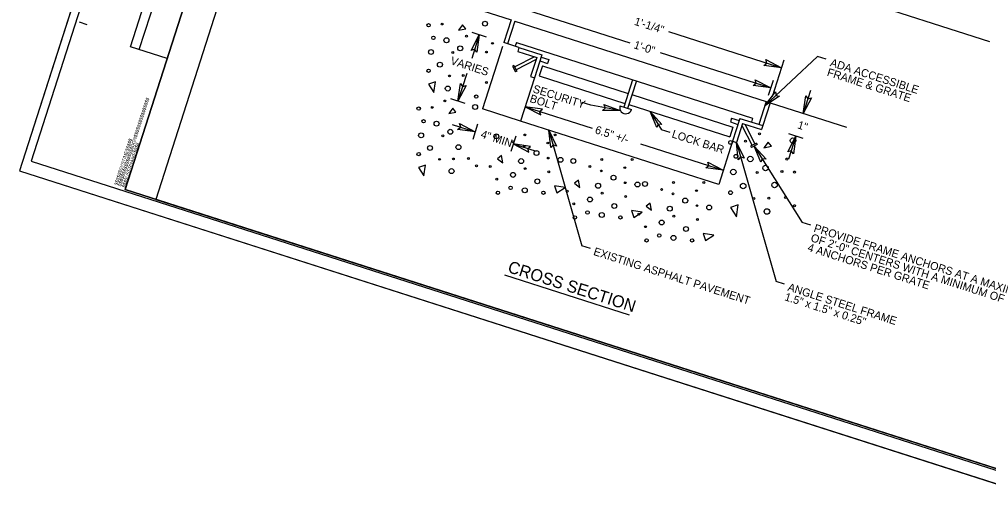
# Model space of a CAD drawing. Extents: x 928111 to 937215, y 684320 to 686530.
# Drawn here: x 933597.6 to 933658.2, y 684605.2 to 684635.2 of the extents above; entities that cross this region are included whole.
import ezdxf

# ---------------------------------------------------------------- set-up
doc = ezdxf.new("R2010")
doc.units = 0
for name, color, linetype in [('Default', 7, 'Continuous'), ('Exist Roads EOP', 7, 'Continuous'), ('Old_Level_2', 7, 'Continuous'), ('Prop Conc 5in Monolithic Keyed In Island', 7, 'Continuous'), ('Prop Dimension', 7, 'Continuous'), ('Prop DSN Text', 7, 'Continuous'), ('Prop Terminator CELL', 7, 'Continuous'), ('Sheet Block Revision CELL', 7, 'Continuous'), ('Sheet Clip Boundary CELL', 7, 'Continuous'), ('Sheet Cutting Line CELL', 7, 'Continuous'), ('Sheet Layout Plan Border', 7, 'Continuous'), ('Sheet Plan CELL', 7, 'Continuous'), ('Sheet Plan Layout CELL', 7, 'Continuous'), ('Sheet Plot Border Inside CELL', 7, 'Continuous'), ('Sheet Plot Border Outside CELL', 7, 'Continuous')]:
    doc.layers.add(name, color=color, linetype=linetype)

msp = doc.modelspace()

# ---------------------------------------------------------------- linework, layer by layer
at = {"layer": 'Default'}
for points in [[(933625.306, 684634.829), (933625.054, 684634.499), (933625.498, 684634.586)], [(933623.172, 684631.132), (933623.507, 684630.607), (933623.612, 684631.278)], [(933624.688, 684629.617), (933624.436, 684629.288), (933624.881, 684629.375)], [(933644.399, 684627.505), (933644.121, 684627.141), (933644.612, 684627.237)], [(933627.489, 684626.465), (933627.819, 684626.213), (933627.732, 684626.658)], [(933622.554, 684625.92), (933622.889, 684625.396), (933622.995, 684626.067)], [(933631.186, 684624.331), (933631.711, 684624.666), (933631.04, 684624.772)], [(933632.298, 684624.924), (933632.628, 684624.672), (933632.541, 684625.116)], [(933636.778, 684623.488), (933637.108, 684623.236), (933637.021, 684623.68)], [(933642.04, 684623.418), (933642.411, 684622.838), (933642.527, 684623.58)], [(933635.995, 684622.789), (933636.52, 684623.125), (933635.849, 684623.23)], [(933640.475, 684621.353), (933641, 684621.689), (933640.329, 684621.794)]]:
    msp.add_lwpolyline(points, close=True, dxfattribs=at)
for centre, radius in [((933626.702, 684634.906), 0.154), ((933623.177, 684634.805), 0.105), ((933624.027, 684634.881), 0.0566), ((933623.482, 684634.019), 0.105), ((933624.293, 684633.867), 0.154), ((933625.55, 684634.12), 0.0566), ((933623.329, 684633.131), 0.154), ((933625.155, 684633.36), 0.154), ((933627.174, 684633.675), 0.0566), ((933624.686, 684633.106), 0.0566), ((933626.791, 684633.131), 0.0566), ((933623.177, 684631.965), 0.105), ((933623.887, 684632.345), 0.154), ((933624.483, 684631.635), 0.0566), ((933625.345, 684631.661), 0.0566), ((933624.378, 684630.848), 0.154), ((933626.791, 684631.23), 0.0566), ((933626.157, 684630.343), 0.105), ((933622.559, 684629.594), 0.105), ((933623.409, 684629.67), 0.0566), ((933624.195, 684630.075), 0.0566), ((933626.084, 684629.695), 0.154), ((933622.864, 684628.807), 0.105), ((933623.675, 684628.655), 0.154), ((933622.712, 684627.92), 0.154), ((933624.068, 684627.895), 0.0566), ((933624.537, 684628.148), 0.154), ((933627.412, 684627.861), 0.154), ((933629.187, 684627.95), 0.0566), ((933631.089, 684627.95), 0.0566), ((933643.854, 684628.012), 0.0626), ((933623.269, 684627.134), 0.154), ((933625.045, 684627.184), 0.154), ((933628.451, 684627.519), 0.0566), ((933629.161, 684627.24), 0.0566), ((933630.632, 684627.443), 0.0566), ((933642.046, 684627.479), 0.116), ((933642.985, 684627.563), 0.0626), ((933645.943, 684627.591), 0.171), ((933622.559, 684626.753), 0.105), ((933629.922, 684626.822), 0.154), ((933642.383, 684626.61), 0.116), ((933643.279, 684626.442), 0.171), ((933623.865, 684626.424), 0.0566), ((933624.728, 684626.449), 0.0566), ((933625.666, 684626.474), 0.0566), ((933626.173, 684626.018), 0.0566), ((933627.031, 684625.972), 0.0566), ((933628.958, 684626.314), 0.154), ((933630.658, 684626.505), 0.0566), ((933631.418, 684626.39), 0.154), ((933632.221, 684626.32), 0.154), ((933633.26, 684625.978), 0.0566), ((933633.996, 684626.409), 0.0566), ((933635.898, 684626.409), 0.0566), ((933644.233, 684625.881), 0.171), ((933645.564, 684626.442), 0.0626), ((933624.613, 684625.688), 0.154), ((933628.451, 684625.452), 0.154), ((933629.212, 684625.845), 0.0566), ((933630.683, 684625.643), 0.0566), ((933633.97, 684625.699), 0.0566), ((933634.731, 684625.28), 0.154), ((933635.441, 684625.902), 0.0566), ((933642.214, 684625.629), 0.171), ((933643.714, 684625.601), 0.0626), ((933645.256, 684625.657), 0.0626), ((933646.041, 684625.629), 0.0626), ((933627.437, 684625.186), 0.0566), ((933629.973, 684625.046), 0.154), ((933633.767, 684624.773), 0.154), ((933635.467, 684624.963), 0.0566), ((933636.227, 684624.849), 0.154), ((933636.701, 684624.884), 0.154), ((933638.476, 684624.973), 0.0566), ((933640.378, 684624.973), 0.0566), ((933642.831, 684624.76), 0.171), ((933644.794, 684624.816), 0.171), ((933627.513, 684624.336), 0.105), ((933628.299, 684624.641), 0.105), ((933629.187, 684624.489), 0.154), ((933630.353, 684624.336), 0.105), ((933631.84, 684624.431), 0.0566), ((933634.021, 684624.304), 0.0566), ((933635.492, 684624.101), 0.0566), ((933637.74, 684624.541), 0.0566), ((933638.45, 684624.263), 0.0566), ((933639.921, 684624.466), 0.0566), ((933642.046, 684624.339), 0.116), ((933632.246, 684623.645), 0.0566), ((933633.26, 684623.911), 0.154), ((933634.782, 684623.505), 0.154), ((933639.211, 684623.844), 0.154), ((933639.947, 684623.527), 0.0566), ((933640.707, 684623.413), 0.154), ((933643.49, 684623.975), 0.0626), ((933644.443, 684624.003), 0.0626), ((933645.48, 684624.031), 0.0626), ((933646.041, 684623.526), 0.0626), ((933633.108, 684623.099), 0.105), ((933633.996, 684622.947), 0.154), ((933636.32, 684622.995), 0.0566), ((933638.247, 684623.337), 0.154), ((933644.317, 684623.162), 0.171), ((933632.322, 684622.795), 0.105), ((933635.162, 684622.795), 0.105), ((933637.74, 684622.475), 0.154), ((933638.501, 684622.868), 0.0566), ((933639.972, 684622.665), 0.0566), ((933636.726, 684622.209), 0.0566), ((933637.588, 684621.663), 0.105), ((933639.262, 684622.069), 0.154), ((933636.802, 684621.359), 0.105), ((933638.476, 684621.511), 0.154), ((933639.642, 684621.359), 0.105)]:
    msp.add_circle(centre, radius, dxfattribs=at)
at = {"layer": 'Exist Roads EOP'}
for p, q in [((933623.567, 684636.672), (933628.328, 684635.146)), ((933628.328, 684635.146), (933627.87, 684633.717)), ((933627.794, 684633.479), (933626.544, 684629.578)), ((933641.304, 684624.847), (933628.924, 684628.815))]:
    msp.add_line(p, q, dxfattribs=at)
at = {"layer": 'Old_Level_2'}
for p, q in [((933628.823, 684633.412), (933628.746, 684633.174)), ((933628.823, 684633.412), (933630.251, 684632.954)), ((933629.802, 684632.836), (933628.559, 684632.196)), ((933629.894, 684632.658), (933628.65, 684632.018)), ((933628.746, 684633.174), (933629.937, 684632.792)), ((933629.937, 684632.792), (933629.555, 684631.602)), ((933630.251, 684632.954), (933629.793, 684631.526)), ((933628.513, 684632.285), (933628.424, 684632.239)), ((933628.424, 684632.239), (933628.607, 684631.883)), ((933628.513, 684632.285), (933628.696, 684631.929)), ((933628.696, 684631.929), (933628.607, 684631.883)), ((933629.555, 684631.602), (933629.793, 684631.526)), ((933642.631, 684628.986), (933642.173, 684627.558)), ((933642.792, 684628.672), (933642.411, 684627.481)), ((933642.631, 684628.986), (933644.059, 684628.528)), ((933642.749, 684628.537), (933643.389, 684627.294)), ((933642.792, 684628.672), (933643.983, 684628.29)), ((933642.927, 684628.628), (933643.567, 684627.385)), ((933644.059, 684628.528), (933643.983, 684628.29)), ((933642.173, 684627.558), (933642.411, 684627.481)), ((933643.656, 684627.431), (933643.3, 684627.248)), ((933643.3, 684627.248), (933643.346, 684627.159)), ((933643.702, 684627.342), (933643.346, 684627.159)), ((933643.656, 684627.431), (933643.702, 684627.342))]:
    msp.add_line(p, q, dxfattribs=at)
at = {"layer": 'Prop Conc 5in Monolithic Keyed In Island'}
for p, q in [((933620.136, 684645.999), (933658.227, 684633.789)), ((933628.566, 684635.069), (933628.108, 684633.641)), ((933628.566, 684635.069), (933644.279, 684630.033)), ((933628.823, 684633.412), (933627.87, 684633.717)), ((933628.661, 684633.726), (933628.585, 684633.488)), ((933628.661, 684633.726), (933643.421, 684628.995)), ((933629.793, 684631.526), (933628.924, 684628.815)), ((933644.279, 684630.033), (933643.821, 684628.604)), ((933644.517, 684629.957), (933644.059, 684628.528)), ((933644.517, 684629.957), (933649.278, 684628.43)), ((933628.924, 684628.815), (933626.544, 684629.578)), ((933643.421, 684628.995), (933643.345, 684628.757)), ((933642.173, 684627.558), (933641.304, 684624.847))]:
    msp.add_line(p, q, dxfattribs=at)
at = {"layer": 'Prop Dimension'}
for p, q in [((933628.84, 684635.922), (933635.744, 684633.709)), ((933626.343, 684634.207), (933625.87, 684632.732)), ((933626.793, 684634.063), (933625.893, 684634.351)), ((933638.169, 684634.409), (933645.22, 684632.149)), ((933637.648, 684633.098), (933644.552, 684630.885)), ((933644.194, 684629.768), (933647.481, 684632.846)), ((933645.372, 684632.625), (933644.638, 684630.333)), ((933625.565, 684631.78), (933625.016, 684630.068)), ((933644.705, 684631.361), (933644.399, 684630.409)), ((933625.466, 684629.923), (933624.566, 684630.212)), ((933647.046, 684630.721), (933646.588, 684629.293)), ((933629.211, 684629.71), (933633.399, 684628.368)), ((933635.156, 684629.479), (933633.308, 684629.812)), ((933637.015, 684629.421), (933637.737, 684628.273)), ((933624.657, 684628.607), (933626.086, 684628.15)), ((933626.238, 684628.626), (933625.933, 684627.673)), ((933628.619, 684627.863), (933628.314, 684626.91)), ((933630.694, 684628.248), (933632.759, 684621.021)), ((933646.13, 684627.864), (933645.672, 684626.436)), ((933646.58, 684627.72), (933645.68, 684628.009)), ((933628.466, 684627.386), (933629.895, 684626.929)), ((933636.425, 684627.398), (933641.591, 684625.742)), ((933642.411, 684627.481), (933644.894, 684618.792)), ((933643.524, 684627.25), (933646.523, 684622.482)), ((933627.913, 684619.21), (933635.706, 684616.712))]:
    msp.add_line(p, q, dxfattribs=at)
at = {"layer": 'Prop DSN Text'}
for p, q in [((933630.205, 684632.811), (933630.681, 684632.659)), ((933630.681, 684632.659), (933630.605, 684632.421)), ((933648.011, 684632.677), (933647.481, 684632.846)), ((933630.291, 684632.259), (933630.092, 684631.64)), ((933630.129, 684632.573), (933630.605, 684632.421)), ((933630.291, 684632.259), (933635.647, 684630.542)), ((933630.092, 684631.64), (933635.449, 684629.923)), ((933635.922, 684631.399), (933635.373, 684629.685)), ((933636.16, 684631.323), (933635.611, 684629.608)), ((933635.885, 684630.466), (933642.194, 684628.443)), ((933633.308, 684629.812), (933632.779, 684629.982)), ((933635.135, 684629.761), (933635.849, 684629.532)), ((933635.687, 684629.847), (933641.996, 684627.824)), ((933642.194, 684628.443), (933641.996, 684627.824)), ((933642.109, 684628.996), (933642.032, 684628.758)), ((933642.032, 684628.758), (933642.509, 684628.605)), ((933642.109, 684628.996), (933642.585, 684628.843)), ((933638.266, 684628.103), (933637.737, 684628.273)), ((933647.053, 684622.313), (933646.523, 684622.482)), ((933633.289, 684620.851), (933632.759, 684621.021)), ((933645.423, 684618.623), (933644.894, 684618.792))]:
    msp.add_line(p, q, dxfattribs=at)
msp.add_arc((933635.492, 684629.647), 0.375, 162.22734, 342.22734, dxfattribs=at)
at = {"layer": 'Prop Terminator CELL'}
for points in [[(933625.836, 684633.235), (933626.343, 684634.207), (933626.194, 684633.114), (933626.054, 684633.304)], [(933644.248, 684632.656), (933645.22, 684632.149), (933644.127, 684632.298), (933644.317, 684632.439)], [(933625.523, 684631.039), (933625.016, 684630.068), (933625.165, 684631.16), (933625.306, 684630.97)], [(933643.58, 684631.392), (933644.552, 684630.885), (933643.459, 684631.034), (933643.649, 684631.175)], [(933645.11, 684630.371), (933644.194, 684629.768), (933644.856, 684630.651), (933644.886, 684630.416)], [(933647.095, 684630.264), (933646.588, 684629.293), (933646.737, 684630.386), (933646.877, 684630.195)], [(933630.297, 684629.558), (933629.211, 684629.71), (933630.187, 684629.196), (933630.114, 684629.421)], [(933634.126, 684629.854), (933635.156, 684629.479), (933634.053, 684629.483), (933634.223, 684629.647)], [(933637.432, 684628.408), (933637.015, 684629.421), (933637.755, 684628.604), (933637.519, 684628.619)], [(933625.114, 684628.656), (933626.086, 684628.15), (933624.993, 684628.298), (933625.183, 684628.439)], [(933630.812, 684627.158), (933630.694, 684628.248), (933631.177, 684627.256), (933630.955, 684627.336)], [(933645.623, 684626.893), (933646.13, 684627.864), (933645.981, 684626.772), (933645.841, 684626.962)], [(933629.552, 684627.234), (933628.466, 684627.386), (933629.442, 684626.872), (933629.369, 684627.097)], [(933642.529, 684626.392), (933642.411, 684627.481), (933642.894, 684626.49), (933642.671, 684626.57)], [(933643.941, 684626.237), (933643.524, 684627.25), (933644.265, 684626.433), (933644.029, 684626.448)], [(933640.619, 684626.249), (933641.591, 684625.742), (933640.498, 684625.891), (933640.688, 684626.032)]]:
    msp.add_lwpolyline(points, close=True, dxfattribs=at)
at = {"layer": 'Sheet Block Revision CELL'}
msp.add_line((933605.103, 684633.281), (933614.756, 684663.398), dxfattribs=at)
msp.add_lwpolyline([(933604.549, 684633.458), (933614.202, 684663.575), (933616.509, 684662.837), (933606.855, 684632.72)], close=True, dxfattribs=at)
at = {"layer": 'Sheet Clip Boundary CELL'}
msp.add_lwpolyline([(933606.134, 684623.92), (933659.462, 684606.826), (933669.7, 684638.766), (933662.491, 684641.077), (933665.073, 684649.133), (933618.954, 684663.916)], close=True, dxfattribs=at)
at = {"layer": 'Sheet Cutting Line CELL'}
for p, q in [((933610.982, 684667.415), (933597.613, 684625.706)), ((933597.613, 684625.706), (933661.739, 684605.151))]:
    msp.add_line(p, q, dxfattribs=at)
at = {"layer": 'Sheet Layout Plan Border'}
msp.add_lwpolyline([(933606.134, 684623.92), (933659.462, 684606.826), (933669.7, 684638.766), (933662.491, 684641.077), (933665.073, 684649.133), (933618.954, 684663.916)], close=True, dxfattribs=at)
at = {"layer": 'Sheet Plan CELL'}
for p, q in [((933601.351, 684635.009), (933601.827, 684634.855)), ((933604.229, 684624.531), (933604.229, 684624.531))]:
    msp.add_line(p, q, dxfattribs=at)
for points in [[(933674.188, 684646.211), (933617.05, 684664.526), (933604.229, 684624.531), (933661.366, 684606.216)], [(933604.229, 684624.531), (933617.048, 684664.525), (933666.567, 684648.654), (933664.735, 684642.938), (933672.354, 684640.495), (933661.366, 684606.216)]]:
    msp.add_lwpolyline(points, close=True, dxfattribs=at)
at = {"layer": 'Sheet Plan Layout CELL'}
msp.add_lwpolyline([(933617.048, 684664.525), (933604.229, 684624.531), (933661.366, 684606.216), (933671.604, 684638.156), (933662.491, 684641.077), (933665.073, 684649.133)], close=True, dxfattribs=at)
at = {"layer": 'Sheet Plot Border Inside CELL'}
msp.add_lwpolyline([(933598.352, 684626.309), (933661.812, 684605.968), (933674.693, 684646.154), (933611.233, 684666.495)], close=True, dxfattribs=at)
at = {"layer": 'Sheet Plot Border Outside CELL'}
msp.add_lwpolyline([(933597.613, 684625.706), (933661.739, 684605.151), (933675.109, 684646.86), (933610.982, 684667.415)], close=True, dxfattribs=at)

# ---------------------------------------------------------------- texts
at = {"layer": 'Prop DSN Text'}
for s, height, p in [('1\'-1/4"', 0.5, (933635.99, 684634.845)), ('1\'-0"', 0.5, (933635.956, 684633.378)), ('VARIES', 0.5, (933624.504, 684632.383)), ('ADA ACCESSIBLE', 0.5, (933648.223, 684632.263)), ('FRAME & GRATE', 0.5, (933648.03, 684631.659)), ('SECURITY ', 0.5, (933629.652, 684630.624)), ('BOLT', 0.5, (933629.458, 684630.02)), ('6.5" +/-', 0.5, (933633.536, 684628.062)), ('1"', 0.5, (933646.185, 684628.372)), ('4" MIN.', 0.5, (933626.396, 684627.788)), ('LOCK BAR', 0.5, (933638.333, 684627.804)), ('PROVIDE FRAME ANCHORS AT A MAXIMUM ', 0.5, (933647.203, 684621.918)), ('OF 2\'-0" CENTERS WITH A MINIMUM OF ', 0.5, (933647.01, 684621.315)), ('EXISTING ASPHALT PAVEMENT', 0.5, (933633.439, 684620.457)), ('4 ANCHORS PER GRATE', 0.5, (933646.816, 684620.711)), ('CROSS SECTION', 0.75, (933628.073, 684619.385)), ('ANGLE STEEL FRAME', 0.5, (933645.574, 684618.228)), ('1.5" x 1.5" x 0.25"', 0.5, (933645.38, 684617.624))]:
    msp.add_text(s, height=height, rotation=342.22734, dxfattribs=at).set_placement(p)
at = {"layer": 'Sheet Plan CELL'}
for s, p in [('$$$$$$$$$$$$$$$$DGN$$$$$$$$$$$$$$$$', (933603.967, 684624.714)), ('$$$$$$SYSTIME$$$$$', (933603.736, 684624.787)), ('$$$$USERNAME$$$$', (933604.217, 684624.634))]:
    msp.add_text(s, height=0.21, rotation=72.22734, dxfattribs=at).set_placement(p)

doc.saveas('drawing.dxf')
